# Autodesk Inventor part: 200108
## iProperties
Created: 2007-10
Part Number: 200108
Document SubType Name: Modeling
Designer: TH
Density: 1.32 g/cm^3
Mass: 29.3271 g
Surface Area: 68.098 cm^2
Volume: 22.2175 cm^3
Material: Polyaryletherketone Resin
Description: BALL SCREW MOUNTING BLOCK
Component Category: Lower Component
Author: TH
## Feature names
1. Extrusion1
2. Fillet1
3. Extrusion2
4. Fillet2
5. Extrusion3
